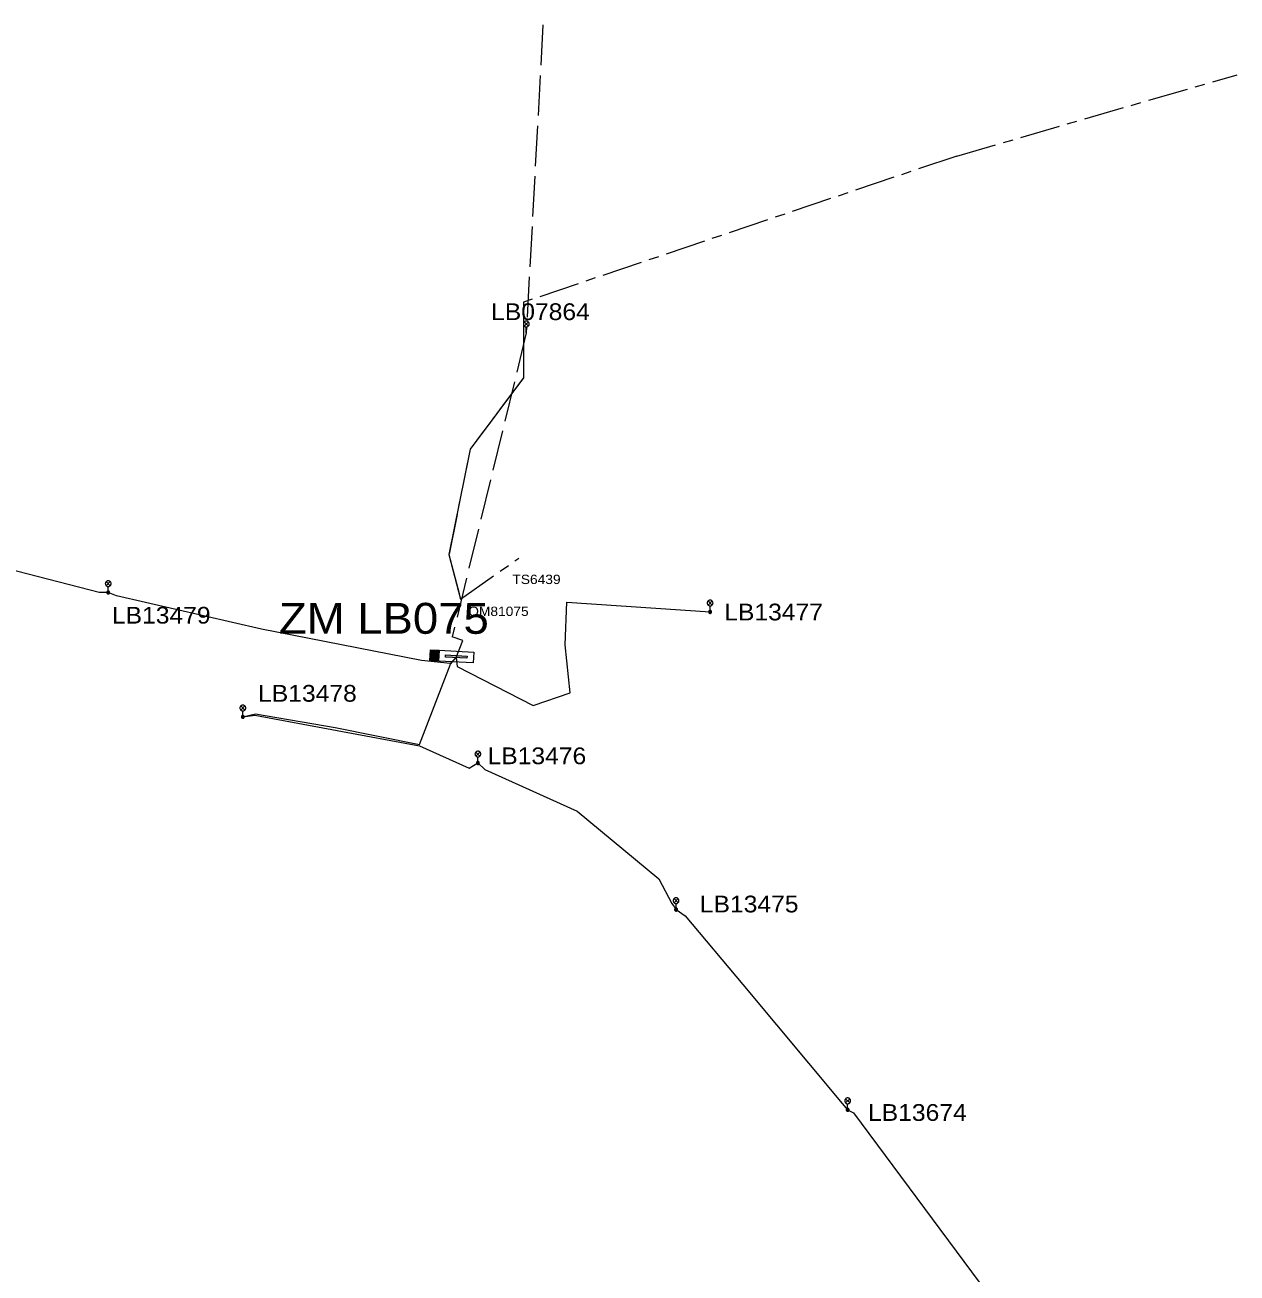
# Model space of a CAD drawing. Extents: x -690018 to -689415, y -972457 to -972107.
# Drawn here: x -689842.5 to -689685.7, y -972289.3 to -972127.9 of the extents above; entities that cross this region are included whole.
import ezdxf

# ---------------------------------------------------------------- set-up
doc = ezdxf.new("R2010")
doc.units = 0
doc.header["$LTSCALE"] = 0.87
doc.linetypes.add('LONG_DASH_SHORT_DASH', pattern=[9.9, 6, -1.2, 1.5, -1.2])
doc.linetypes.add('LONG_DASHED', pattern=[7.5, 6, -1.5])
doc.layers.add('1', color=7, linetype='Continuous', lineweight=13)

msp = doc.modelspace()

# ---------------------------------------------------------------- hatches: boundary and pattern name
at = {"layer": '1'}
for points in [[(-689790.008, -972208.666), (-689788.89, -972208.728), (-689788.966, -972210.125), (-689790.084, -972210.064)], [(-689789.755, -972209.732), (-689789.717, -972209.033), (-689789.177, -972209.062), (-689789.184, -972209.178), (-689789.564, -972209.158), (-689789.572, -972209.311), (-689789.242, -972209.329), (-689789.249, -972209.445), (-689789.579, -972209.427), (-689789.589, -972209.613), (-689789.208, -972209.634), (-689789.215, -972209.761)], [(-689788.082, -972209.332), (-689785.286, -972209.485), (-689785.301, -972209.765), (-689788.097, -972209.612)]]:
    msp.add_hatch(color=256, dxfattribs=at).paths.add_polyline_path(points)

# ---------------------------------------------------------------- linework, layer by layer
at = {"layer": '1', "linetype": 'LONG_DASHED'}
for p, q in [((-689775.48, -972127.88), (-689777.63, -972167.7)), ((-689777.63, -972167.7), (-689787.2, -972206.98))]:
    msp.add_line(p, q, dxfattribs=at)
at = {"layer": '1', "linetype": 'LONG_DASH_SHORT_DASH'}
for p, q in [((-689721.963, -972144.828), (-689685.729, -972134.31)), ((-689778.009, -972173.498), (-689784.875, -972182.742)), ((-689784.875, -972182.742), (-689787.634, -972196.357)), ((-689787.634, -972196.357), (-689786.125, -972202.128)), ((-689786.125, -972202.128), (-689778.616, -972196.822))]:
    msp.add_line(p, q, dxfattribs=at)
at = {"layer": '1'}
for p, q in [((-689777.975, -972163.724), (-689778.009, -972173.498)), ((-689777.895, -972166.285), (-689777.365, -972166.815)), ((-689777.895, -972166.815), (-689777.365, -972166.285)), ((-689777.63, -972167.7), (-689777.63, -972166.925)), ((-689778.009, -972173.498), (-689784.875, -972182.742)), ((-689784.875, -972182.742), (-689787.634, -972196.357)), ((-689787.634, -972196.357), (-689786.125, -972202.128)), ((-689831.955, -972199.855), (-689831.425, -972200.385)), ((-689831.955, -972200.385), (-689831.425, -972199.855)), ((-689831.69, -972201.27), (-689831.69, -972200.495)), ((-689754.125, -972202.365), (-689753.595, -972202.895)), ((-689754.125, -972202.895), (-689753.595, -972202.365)), ((-689753.86, -972203.78), (-689753.86, -972203.005)), ((-689814.545, -972215.935), (-689814.015, -972216.465)), ((-689814.545, -972216.465), (-689814.015, -972215.935)), ((-689814.28, -972217.35), (-689814.28, -972216.575)), ((-689784.155, -972221.895), (-689783.625, -972222.425)), ((-689784.155, -972222.425), (-689783.625, -972221.895)), ((-689783.89, -972223.31), (-689783.89, -972222.535)), ((-689758.525, -972240.855), (-689757.995, -972241.385)), ((-689758.525, -972241.385), (-689757.995, -972240.855)), ((-689758.26, -972242.27), (-689758.26, -972241.495)), ((-689736.345, -972266.735), (-689735.815, -972267.265)), ((-689736.345, -972267.265), (-689735.815, -972266.735)), ((-689736.08, -972268.15), (-689736.08, -972267.375))]:
    msp.add_line(p, q, dxfattribs=at)
at = {"layer": '1', "linetype": 'LONG_DASH_SHORT_DASH'}
msp.add_lwpolyline([(-689721.963, -972144.828), (-689777.975, -972163.724), (-689778.009, -972173.498)], dxfattribs=at)
at = {"layer": '1'}
for points in [[(-689777.255, -972166.55), (-689777.261, -972166.485), (-689777.278, -972166.422), (-689777.305, -972166.362), (-689777.343, -972166.309), (-689777.389, -972166.263), (-689777.442, -972166.225), (-689777.502, -972166.198), (-689777.565, -972166.181), (-689777.63, -972166.175), (-689777.695, -972166.181), (-689777.758, -972166.198), (-689777.818, -972166.225), (-689777.871, -972166.263), (-689777.917, -972166.309), (-689777.955, -972166.362), (-689777.982, -972166.422), (-689777.999, -972166.485), (-689778.005, -972166.55), (-689777.999, -972166.615), (-689777.982, -972166.678), (-689777.955, -972166.738), (-689777.917, -972166.791), (-689777.871, -972166.837), (-689777.818, -972166.875), (-689777.758, -972166.902), (-689777.695, -972166.919), (-689777.63, -972166.925), (-689777.565, -972166.919), (-689777.502, -972166.902), (-689777.442, -972166.875), (-689777.389, -972166.837), (-689777.343, -972166.791), (-689777.305, -972166.738), (-689777.278, -972166.678), (-689777.261, -972166.615)], [(-689831.315, -972200.12), (-689831.321, -972200.055), (-689831.338, -972199.992), (-689831.365, -972199.932), (-689831.403, -972199.879), (-689831.449, -972199.833), (-689831.503, -972199.795), (-689831.562, -972199.768), (-689831.625, -972199.751), (-689831.69, -972199.745), (-689831.755, -972199.751), (-689831.818, -972199.768), (-689831.878, -972199.795), (-689831.931, -972199.833), (-689831.977, -972199.879), (-689832.015, -972199.932), (-689832.042, -972199.992), (-689832.059, -972200.055), (-689832.065, -972200.12), (-689832.059, -972200.185), (-689832.042, -972200.248), (-689832.015, -972200.308), (-689831.977, -972200.361), (-689831.931, -972200.407), (-689831.878, -972200.445), (-689831.818, -972200.472), (-689831.755, -972200.489), (-689831.69, -972200.495), (-689831.625, -972200.489), (-689831.562, -972200.472), (-689831.503, -972200.445), (-689831.449, -972200.407), (-689831.403, -972200.361), (-689831.365, -972200.308), (-689831.338, -972200.248), (-689831.321, -972200.185)], [(-689831.5, -972201.27), (-689831.503, -972201.237), (-689831.511, -972201.205), (-689831.525, -972201.175), (-689831.544, -972201.148), (-689831.568, -972201.124), (-689831.595, -972201.105), (-689831.625, -972201.091), (-689831.657, -972201.083), (-689831.69, -972201.08), (-689831.723, -972201.083), (-689831.755, -972201.091), (-689831.785, -972201.105), (-689831.812, -972201.124), (-689831.836, -972201.148), (-689831.855, -972201.175), (-689831.869, -972201.205), (-689831.877, -972201.237), (-689831.88, -972201.27), (-689831.877, -972201.303), (-689831.869, -972201.335), (-689831.855, -972201.365), (-689831.836, -972201.392), (-689831.812, -972201.416), (-689831.785, -972201.435), (-689831.755, -972201.449), (-689831.723, -972201.457), (-689831.69, -972201.46), (-689831.657, -972201.457), (-689831.625, -972201.449), (-689831.595, -972201.435), (-689831.568, -972201.416), (-689831.544, -972201.392), (-689831.525, -972201.365), (-689831.511, -972201.335), (-689831.503, -972201.303)], [(-689831.64, -972201.27), (-689831.641, -972201.261), (-689831.643, -972201.253), (-689831.647, -972201.245), (-689831.652, -972201.238), (-689831.658, -972201.232), (-689831.665, -972201.227), (-689831.673, -972201.223), (-689831.681, -972201.221), (-689831.69, -972201.22), (-689831.699, -972201.221), (-689831.707, -972201.223), (-689831.715, -972201.227), (-689831.722, -972201.232), (-689831.728, -972201.238), (-689831.733, -972201.245), (-689831.737, -972201.253), (-689831.739, -972201.261), (-689831.74, -972201.27), (-689831.739, -972201.279), (-689831.737, -972201.287), (-689831.733, -972201.295), (-689831.728, -972201.302), (-689831.722, -972201.308), (-689831.715, -972201.313), (-689831.707, -972201.317), (-689831.699, -972201.319), (-689831.69, -972201.32), (-689831.681, -972201.319), (-689831.673, -972201.317), (-689831.665, -972201.313), (-689831.658, -972201.308), (-689831.652, -972201.302), (-689831.647, -972201.295), (-689831.643, -972201.287), (-689831.641, -972201.279)], [(-689753.485, -972202.63), (-689753.491, -972202.565), (-689753.508, -972202.502), (-689753.535, -972202.442), (-689753.573, -972202.389), (-689753.619, -972202.343), (-689753.672, -972202.305), (-689753.732, -972202.278), (-689753.795, -972202.261), (-689753.86, -972202.255), (-689753.925, -972202.261), (-689753.988, -972202.278), (-689754.048, -972202.305), (-689754.101, -972202.343), (-689754.147, -972202.389), (-689754.185, -972202.442), (-689754.212, -972202.502), (-689754.229, -972202.565), (-689754.235, -972202.63), (-689754.229, -972202.695), (-689754.212, -972202.758), (-689754.185, -972202.818), (-689754.147, -972202.871), (-689754.101, -972202.917), (-689754.048, -972202.955), (-689753.988, -972202.982), (-689753.925, -972202.999), (-689753.86, -972203.005), (-689753.795, -972202.999), (-689753.732, -972202.982), (-689753.672, -972202.955), (-689753.619, -972202.917), (-689753.573, -972202.871), (-689753.535, -972202.818), (-689753.508, -972202.758), (-689753.491, -972202.695)], [(-689753.67, -972203.78), (-689753.673, -972203.747), (-689753.681, -972203.715), (-689753.695, -972203.685), (-689753.714, -972203.658), (-689753.738, -972203.634), (-689753.765, -972203.615), (-689753.795, -972203.601), (-689753.827, -972203.593), (-689753.86, -972203.59), (-689753.893, -972203.593), (-689753.925, -972203.601), (-689753.955, -972203.615), (-689753.982, -972203.634), (-689754.006, -972203.658), (-689754.025, -972203.685), (-689754.039, -972203.715), (-689754.047, -972203.747), (-689754.05, -972203.78), (-689754.047, -972203.813), (-689754.039, -972203.845), (-689754.025, -972203.875), (-689754.006, -972203.902), (-689753.982, -972203.926), (-689753.955, -972203.945), (-689753.925, -972203.959), (-689753.893, -972203.967), (-689753.86, -972203.97), (-689753.827, -972203.967), (-689753.795, -972203.959), (-689753.765, -972203.945), (-689753.738, -972203.926), (-689753.714, -972203.902), (-689753.695, -972203.875), (-689753.681, -972203.845), (-689753.673, -972203.813)], [(-689753.81, -972203.78), (-689753.811, -972203.771), (-689753.813, -972203.763), (-689753.817, -972203.755), (-689753.822, -972203.748), (-689753.828, -972203.742), (-689753.835, -972203.737), (-689753.843, -972203.733), (-689753.851, -972203.731), (-689753.86, -972203.73), (-689753.869, -972203.731), (-689753.877, -972203.733), (-689753.885, -972203.737), (-689753.892, -972203.742), (-689753.898, -972203.748), (-689753.903, -972203.755), (-689753.907, -972203.763), (-689753.909, -972203.771), (-689753.91, -972203.78), (-689753.909, -972203.789), (-689753.907, -972203.797), (-689753.903, -972203.805), (-689753.898, -972203.812), (-689753.892, -972203.818), (-689753.885, -972203.823), (-689753.877, -972203.827), (-689753.869, -972203.829), (-689753.86, -972203.83), (-689753.851, -972203.829), (-689753.843, -972203.827), (-689753.835, -972203.823), (-689753.828, -972203.818), (-689753.822, -972203.812), (-689753.817, -972203.805), (-689753.813, -972203.797), (-689753.811, -972203.789)], [(-689790.008, -972208.666), (-689788.89, -972208.728), (-689788.966, -972210.125), (-689790.084, -972210.064)], [(-689790.008, -972208.666), (-689788.89, -972208.728), (-689788.966, -972210.125), (-689790.084, -972210.064)], [(-689789.755, -972209.732), (-689789.717, -972209.033), (-689789.177, -972209.062), (-689789.184, -972209.178), (-689789.564, -972209.158), (-689789.572, -972209.311), (-689789.242, -972209.329), (-689789.249, -972209.445), (-689789.579, -972209.427), (-689789.589, -972209.613), (-689789.208, -972209.634), (-689789.215, -972209.761)], [(-689788.082, -972209.332), (-689785.286, -972209.485), (-689785.301, -972209.765), (-689788.097, -972209.612)], [(-689813.905, -972216.2), (-689813.911, -972216.135), (-689813.928, -972216.072), (-689813.955, -972216.013), (-689813.993, -972215.959), (-689814.039, -972215.913), (-689814.092, -972215.875), (-689814.152, -972215.848), (-689814.215, -972215.831), (-689814.28, -972215.825), (-689814.345, -972215.831), (-689814.408, -972215.848), (-689814.468, -972215.875), (-689814.521, -972215.913), (-689814.567, -972215.959), (-689814.605, -972216.013), (-689814.632, -972216.072), (-689814.649, -972216.135), (-689814.655, -972216.2), (-689814.649, -972216.265), (-689814.632, -972216.328), (-689814.605, -972216.388), (-689814.567, -972216.441), (-689814.521, -972216.487), (-689814.468, -972216.525), (-689814.408, -972216.552), (-689814.345, -972216.569), (-689814.28, -972216.575), (-689814.215, -972216.569), (-689814.152, -972216.552), (-689814.092, -972216.525), (-689814.039, -972216.487), (-689813.993, -972216.441), (-689813.955, -972216.388), (-689813.928, -972216.328), (-689813.911, -972216.265)], [(-689814.09, -972217.35), (-689814.093, -972217.317), (-689814.101, -972217.285), (-689814.115, -972217.255), (-689814.134, -972217.228), (-689814.158, -972217.204), (-689814.185, -972217.185), (-689814.215, -972217.171), (-689814.247, -972217.163), (-689814.28, -972217.16), (-689814.313, -972217.163), (-689814.345, -972217.171), (-689814.375, -972217.185), (-689814.402, -972217.204), (-689814.426, -972217.228), (-689814.445, -972217.255), (-689814.459, -972217.285), (-689814.467, -972217.317), (-689814.47, -972217.35), (-689814.467, -972217.383), (-689814.459, -972217.415), (-689814.445, -972217.445), (-689814.426, -972217.472), (-689814.402, -972217.496), (-689814.375, -972217.515), (-689814.345, -972217.529), (-689814.313, -972217.537), (-689814.28, -972217.54), (-689814.247, -972217.537), (-689814.215, -972217.529), (-689814.185, -972217.515), (-689814.158, -972217.496), (-689814.134, -972217.472), (-689814.115, -972217.445), (-689814.101, -972217.415), (-689814.093, -972217.383)], [(-689814.23, -972217.35), (-689814.231, -972217.341), (-689814.233, -972217.333), (-689814.237, -972217.325), (-689814.242, -972217.318), (-689814.248, -972217.312), (-689814.255, -972217.307), (-689814.263, -972217.303), (-689814.271, -972217.301), (-689814.28, -972217.3), (-689814.289, -972217.301), (-689814.297, -972217.303), (-689814.305, -972217.307), (-689814.312, -972217.312), (-689814.318, -972217.318), (-689814.323, -972217.325), (-689814.327, -972217.333), (-689814.329, -972217.341), (-689814.33, -972217.35), (-689814.329, -972217.359), (-689814.327, -972217.367), (-689814.323, -972217.375), (-689814.318, -972217.382), (-689814.312, -972217.388), (-689814.305, -972217.393), (-689814.297, -972217.397), (-689814.289, -972217.399), (-689814.28, -972217.4), (-689814.271, -972217.399), (-689814.263, -972217.397), (-689814.255, -972217.393), (-689814.248, -972217.388), (-689814.242, -972217.382), (-689814.237, -972217.375), (-689814.233, -972217.367), (-689814.231, -972217.359)], [(-689783.515, -972222.16), (-689783.521, -972222.095), (-689783.538, -972222.032), (-689783.565, -972221.972), (-689783.603, -972221.919), (-689783.649, -972221.873), (-689783.702, -972221.835), (-689783.762, -972221.808), (-689783.825, -972221.791), (-689783.89, -972221.785), (-689783.955, -972221.791), (-689784.018, -972221.808), (-689784.078, -972221.835), (-689784.131, -972221.873), (-689784.177, -972221.919), (-689784.215, -972221.972), (-689784.242, -972222.032), (-689784.259, -972222.095), (-689784.265, -972222.16), (-689784.259, -972222.225), (-689784.242, -972222.288), (-689784.215, -972222.348), (-689784.177, -972222.401), (-689784.131, -972222.447), (-689784.078, -972222.485), (-689784.018, -972222.512), (-689783.955, -972222.529), (-689783.89, -972222.535), (-689783.825, -972222.529), (-689783.762, -972222.512), (-689783.702, -972222.485), (-689783.649, -972222.447), (-689783.603, -972222.401), (-689783.565, -972222.348), (-689783.538, -972222.288), (-689783.521, -972222.225)], [(-689783.7, -972223.31), (-689783.703, -972223.277), (-689783.711, -972223.245), (-689783.725, -972223.215), (-689783.744, -972223.188), (-689783.768, -972223.164), (-689783.795, -972223.145), (-689783.825, -972223.131), (-689783.857, -972223.123), (-689783.89, -972223.12), (-689783.923, -972223.123), (-689783.955, -972223.131), (-689783.985, -972223.145), (-689784.012, -972223.164), (-689784.036, -972223.188), (-689784.055, -972223.215), (-689784.069, -972223.245), (-689784.077, -972223.277), (-689784.08, -972223.31), (-689784.077, -972223.343), (-689784.069, -972223.375), (-689784.055, -972223.405), (-689784.036, -972223.432), (-689784.012, -972223.456), (-689783.985, -972223.475), (-689783.955, -972223.489), (-689783.923, -972223.497), (-689783.89, -972223.5), (-689783.857, -972223.497), (-689783.825, -972223.489), (-689783.795, -972223.475), (-689783.768, -972223.456), (-689783.744, -972223.432), (-689783.725, -972223.405), (-689783.711, -972223.375), (-689783.703, -972223.343)], [(-689783.84, -972223.31), (-689783.841, -972223.301), (-689783.843, -972223.293), (-689783.847, -972223.285), (-689783.852, -972223.278), (-689783.858, -972223.272), (-689783.865, -972223.267), (-689783.873, -972223.263), (-689783.881, -972223.261), (-689783.89, -972223.26), (-689783.899, -972223.261), (-689783.907, -972223.263), (-689783.915, -972223.267), (-689783.922, -972223.272), (-689783.928, -972223.278), (-689783.933, -972223.285), (-689783.937, -972223.293), (-689783.939, -972223.301), (-689783.94, -972223.31), (-689783.939, -972223.319), (-689783.937, -972223.327), (-689783.933, -972223.335), (-689783.928, -972223.342), (-689783.922, -972223.348), (-689783.915, -972223.353), (-689783.907, -972223.357), (-689783.899, -972223.359), (-689783.89, -972223.36), (-689783.881, -972223.359), (-689783.873, -972223.357), (-689783.865, -972223.353), (-689783.858, -972223.348), (-689783.852, -972223.342), (-689783.847, -972223.335), (-689783.843, -972223.327), (-689783.841, -972223.319)], [(-689757.885, -972241.12), (-689757.891, -972241.055), (-689757.908, -972240.992), (-689757.935, -972240.932), (-689757.973, -972240.879), (-689758.019, -972240.833), (-689758.072, -972240.795), (-689758.132, -972240.768), (-689758.195, -972240.751), (-689758.26, -972240.745), (-689758.325, -972240.751), (-689758.388, -972240.768), (-689758.448, -972240.795), (-689758.501, -972240.833), (-689758.547, -972240.879), (-689758.585, -972240.932), (-689758.612, -972240.992), (-689758.629, -972241.055), (-689758.635, -972241.12), (-689758.629, -972241.185), (-689758.612, -972241.248), (-689758.585, -972241.308), (-689758.547, -972241.361), (-689758.501, -972241.407), (-689758.448, -972241.445), (-689758.388, -972241.472), (-689758.325, -972241.489), (-689758.26, -972241.495), (-689758.195, -972241.489), (-689758.132, -972241.472), (-689758.072, -972241.445), (-689758.019, -972241.407), (-689757.973, -972241.361), (-689757.935, -972241.308), (-689757.908, -972241.248), (-689757.891, -972241.185)], [(-689758.07, -972242.27), (-689758.073, -972242.237), (-689758.081, -972242.205), (-689758.095, -972242.175), (-689758.114, -972242.148), (-689758.138, -972242.124), (-689758.165, -972242.105), (-689758.195, -972242.091), (-689758.227, -972242.083), (-689758.26, -972242.08), (-689758.293, -972242.083), (-689758.325, -972242.091), (-689758.355, -972242.105), (-689758.382, -972242.124), (-689758.406, -972242.148), (-689758.425, -972242.175), (-689758.439, -972242.205), (-689758.447, -972242.237), (-689758.45, -972242.27), (-689758.447, -972242.303), (-689758.439, -972242.335), (-689758.425, -972242.365), (-689758.406, -972242.392), (-689758.382, -972242.416), (-689758.355, -972242.435), (-689758.325, -972242.449), (-689758.293, -972242.457), (-689758.26, -972242.46), (-689758.227, -972242.457), (-689758.195, -972242.449), (-689758.165, -972242.435), (-689758.138, -972242.416), (-689758.114, -972242.392), (-689758.095, -972242.365), (-689758.081, -972242.335), (-689758.073, -972242.303)], [(-689758.21, -972242.27), (-689758.211, -972242.261), (-689758.213, -972242.253), (-689758.217, -972242.245), (-689758.222, -972242.238), (-689758.228, -972242.232), (-689758.235, -972242.227), (-689758.243, -972242.223), (-689758.251, -972242.221), (-689758.26, -972242.22), (-689758.269, -972242.221), (-689758.277, -972242.223), (-689758.285, -972242.227), (-689758.292, -972242.232), (-689758.298, -972242.238), (-689758.303, -972242.245), (-689758.307, -972242.253), (-689758.309, -972242.261), (-689758.31, -972242.27), (-689758.309, -972242.279), (-689758.307, -972242.287), (-689758.303, -972242.295), (-689758.298, -972242.302), (-689758.292, -972242.308), (-689758.285, -972242.313), (-689758.277, -972242.317), (-689758.269, -972242.319), (-689758.26, -972242.32), (-689758.251, -972242.319), (-689758.243, -972242.317), (-689758.235, -972242.313), (-689758.228, -972242.308), (-689758.222, -972242.302), (-689758.217, -972242.295), (-689758.213, -972242.287), (-689758.211, -972242.279)], [(-689735.705, -972267), (-689735.711, -972266.935), (-689735.728, -972266.872), (-689735.755, -972266.812), (-689735.793, -972266.759), (-689735.839, -972266.713), (-689735.892, -972266.675), (-689735.952, -972266.648), (-689736.015, -972266.631), (-689736.08, -972266.625), (-689736.145, -972266.631), (-689736.208, -972266.648), (-689736.268, -972266.675), (-689736.321, -972266.713), (-689736.367, -972266.759), (-689736.405, -972266.812), (-689736.432, -972266.872), (-689736.449, -972266.935), (-689736.455, -972267), (-689736.449, -972267.065), (-689736.432, -972267.128), (-689736.405, -972267.188), (-689736.367, -972267.241), (-689736.321, -972267.287), (-689736.268, -972267.325), (-689736.208, -972267.352), (-689736.145, -972267.369), (-689736.08, -972267.375), (-689736.015, -972267.369), (-689735.952, -972267.352), (-689735.892, -972267.325), (-689735.839, -972267.287), (-689735.793, -972267.241), (-689735.755, -972267.188), (-689735.728, -972267.128), (-689735.711, -972267.065)], [(-689735.89, -972268.15), (-689735.893, -972268.117), (-689735.901, -972268.085), (-689735.915, -972268.055), (-689735.934, -972268.028), (-689735.958, -972268.004), (-689735.985, -972267.985), (-689736.015, -972267.971), (-689736.047, -972267.963), (-689736.08, -972267.96), (-689736.113, -972267.963), (-689736.145, -972267.971), (-689736.175, -972267.985), (-689736.202, -972268.004), (-689736.226, -972268.028), (-689736.245, -972268.055), (-689736.259, -972268.085), (-689736.267, -972268.117), (-689736.27, -972268.15), (-689736.267, -972268.183), (-689736.259, -972268.215), (-689736.245, -972268.245), (-689736.226, -972268.272), (-689736.202, -972268.296), (-689736.175, -972268.315), (-689736.145, -972268.329), (-689736.113, -972268.337), (-689736.08, -972268.34), (-689736.047, -972268.337), (-689736.015, -972268.329), (-689735.985, -972268.315), (-689735.958, -972268.296), (-689735.934, -972268.272), (-689735.915, -972268.245), (-689735.901, -972268.215), (-689735.893, -972268.183)], [(-689736.03, -972268.15), (-689736.031, -972268.141), (-689736.033, -972268.133), (-689736.037, -972268.125), (-689736.042, -972268.118), (-689736.048, -972268.112), (-689736.055, -972268.107), (-689736.063, -972268.103), (-689736.071, -972268.101), (-689736.08, -972268.1), (-689736.089, -972268.101), (-689736.097, -972268.103), (-689736.105, -972268.107), (-689736.112, -972268.112), (-689736.118, -972268.118), (-689736.123, -972268.125), (-689736.127, -972268.133), (-689736.129, -972268.141), (-689736.13, -972268.15), (-689736.129, -972268.159), (-689736.127, -972268.167), (-689736.123, -972268.175), (-689736.118, -972268.182), (-689736.112, -972268.188), (-689736.105, -972268.193), (-689736.097, -972268.197), (-689736.089, -972268.199), (-689736.08, -972268.2), (-689736.071, -972268.199), (-689736.063, -972268.197), (-689736.055, -972268.193), (-689736.048, -972268.188), (-689736.042, -972268.182), (-689736.037, -972268.175), (-689736.033, -972268.167), (-689736.031, -972268.159)]]:
    msp.add_lwpolyline(points, close=True, dxfattribs=at)
for points in [[(-689831.69, -972201.27), (-689832.862, -972201.27), (-689847.448, -972197.511), (-689860.303, -972195.527), (-689863.452, -972194.661), (-689864.83, -972193.77)], [(-689786.699, -972209.688), (-689787.489, -972210.457), (-689791.191, -972210.05), (-689811.885, -972206.021), (-689830.603, -972201.707), (-689831.69, -972201.27)], [(-689786.699, -972209.688), (-689786.588, -972210.837), (-689776.763, -972215.864), (-689771.949, -972214.258), (-689772.601, -972208.048), (-689772.375, -972202.531), (-689753.86, -972203.78)], [(-689786.699, -972209.688), (-689785.816, -972207.49), (-689787.2, -972206.98)], [(-689814.28, -972217.35), (-689812.653, -972216.942), (-689802.34, -972218.744), (-689791.452, -972220.925), (-689787.428, -972210.537), (-689786.699, -972209.688)], [(-689788.89, -972208.728), (-689784.416, -972208.972), (-689784.493, -972210.37), (-689788.966, -972210.125)], [(-689814.28, -972217.35), (-689812.731, -972217.126), (-689791.447, -972221.102), (-689785.017, -972223.962), (-689783.89, -972223.31)], [(-689783.89, -972223.31), (-689782.989, -972224.139), (-689771.065, -972229.563), (-689760.507, -972238.274), (-689758.821, -972241.466), (-689758.26, -972242.27)], [(-689758.26, -972242.27), (-689757.083, -972243.083), (-689749.644, -972251.972), (-689736.791, -972267.333), (-689736.08, -972268.15)], [(-689736.081, -972268.142), (-689735.301, -972268.549), (-689716.979, -972293.281), (-689716.42, -972294.08)]]:
    msp.add_lwpolyline(points, dxfattribs=at)

# ---------------------------------------------------------------- texts
at = {"layer": '1', "width": 1.1}
for s, height, p in [('LB07864', 2.167, (-689782.18, -972166.041)), ('TS6439', 1.21, (-689779.427, -972200.175)), ('LB13479', 2.167, (-689831.21, -972205.289)), ('ZM LB075', 4, (-689809.62, -972206.607)), ('OM81075', 1.21, (-689785.14, -972204.306)), ('LB13477', 2.167, (-689752.035, -972204.875)), ('LB13478', 2.167, (-689812.313, -972215.387)), ('LB13476', 2.167, (-689782.644, -972223.47)), ('LB13475', 2.167, (-689755.194, -972242.634)), ('LB13674', 2.167, (-689733.446, -972269.593))]:
    msp.add_text(s, height=height, dxfattribs=at).set_placement(p)

doc.saveas('drawing.dxf')
